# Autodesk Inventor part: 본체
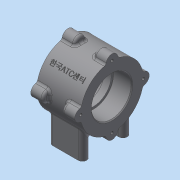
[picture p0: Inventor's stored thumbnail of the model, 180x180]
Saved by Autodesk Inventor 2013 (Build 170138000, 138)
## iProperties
Created: 2015-03
Part Number: 본체
Material: 일반
Document SubType Name: Modeling
Designer: 교육생
Density: 1 g/cm^3
Author: 교육생
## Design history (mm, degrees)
sketch "스케치1"
  geometry: L1 (19, -31.749)-(19, -56); L2 (19, -56)-(29, -56); L3 (29, -56)-(29, -22.978); L4 (-29, -22.978)-(-29, -56); L5 (-29, -56)-(-19, -56); L6 (-19, -56)-(-19, -31.749); A1 r 37 centre (0, 0) between (19, -31.749) and (29, -22.978); 3 further points
  constraints: 12 end point, 4 parallel, 4 point on circle, 3 horizontal alignment, 2 midpoint, 2 perpendicular, 1 centre point, 1 coincident, 1 vertical
  dimensions: "d0" = 74 diameter of A1; "d4" = 10 distance of L1.end L2.end; "d5" = 56 distance from line of L2 point (0, 0); "d6" = 48 distance of point (24, -56) point (-24, -56)
extrude "돌출1" new body sketch "스케치1" stored distance "d2" = 52; taper "d3" = 0 deg
extrude "돌출2" join sketch "스케치1" stored distance "d7" = 40; taper "d8" = 0 deg
sketch "스케치2"
  geometry: A1 r 37 centre (0, 0) between (0, 37) and (-6.969, 36.338) reference; A2 r 7 centre (0, 37) between (6.969, 36.338) and (-6.969, 36.338)
  constraints: 5 point on circle, 1 centre point, 1 vertical alignment
  dimensions: "d9" = 7 radius of A2
extrude "돌출3" join sketch "스케치2" distance "d11" = 15; taper "d12" = 0 deg
hole "구멍1" diameter "d15" = 3.242; stored, may be unused: countersink angle "d19" = 90 deg, drill point angle "d21" = 118 deg; dims "d13" = 10, "d14" = 10, "d16" = 8, "d17" = 4, "d18" = 2, "d20" = 11
fillet "모깎기1" dims "d25" = 5
fillet "모깎기2" dims "d26" = 3
fillet "모깎기3" dims "d27" = 3
fillet "모깎기4" dims "d28" = 3
fillet "모깎기5" dims "d29" = 3
fillet "모깎기6" dims "d30" = 3
hole "구멍3" diameter "d42" = 4.134; stored, may be unused: countersink angle "d46" = 90 deg, drill point angle "d48" = 118 deg; dims "d40" = 10, "d41" = 10, "d43" = 6, "d44" = 4, "d45" = 2, "d47" = 8
hole "구멍4" diameter "d51" = 4.134; stored, may be unused: countersink angle "d55" = 90 deg, drill point angle "d57" = 118 deg; dims "d49" = 10, "d50" = 10, "d52" = 6, "d53" = 4, "d54" = 2, "d56" = 8
hole "구멍5" diameter "d60" = 4.134; stored, may be unused: countersink angle "d64" = 90 deg, drill point angle "d66" = 118 deg; dims "d58" = 10, "d59" = 10, "d61" = 6, "d62" = 4, "d63" = 2, "d65" = 8
hole "구멍6" diameter "d69" = 4.134; stored, may be unused: countersink angle "d73" = 90 deg, drill point angle "d75" = 118 deg; dims "d67" = 10, "d68" = 10, "d70" = 6, "d71" = 4, "d72" = 2, "d74" = 8
hole "구멍7" diameter "d78" = 42; stored, may be unused: countersink angle "d82" = 90 deg, drill point angle "d84" = 118 deg; dims "d76" = 10, "d77" = 10, "d79" = 6, "d80" = 47, "d81" = 22, "d83" = 8
hole "구멍8" diameter "d87" = 47; stored, may be unused: countersink angle "d91" = 90 deg, drill point angle "d93" = 0 deg; dims "d85" = 10, "d86" = 10, "d88" = 6, "d89" = 47, "d90" = 22, "d92" = 22
fillet "모깎기7" dims "d94" = 0.3
chamfer "모따기1" distance "d95" = 1; stored, may be unused: second distance "d96" = 2, angle "d97" = 45 deg
node "작업 평면2"
  node "작업 평면1"
sketch "스케치4"
  geometry: L1 (-26, 18.921)-(-26, -18.921) reference; 3 further points
  constraints: 1 horizontal alignment, 1 midpoint, 1 other
  dimensions: "d101" = 26 distance from line of point (0, 0) L1
feature "엠보싱1" sketch "스케치4" dims "d102" = 0.5, "d103" = 0
node "솔리드1"
pattern_circular "원형 패턴1" dims angle "d23" = 360 deg
mirror "대칭1"
other parameters: "d98" = 45 deg, "d99" = 37
